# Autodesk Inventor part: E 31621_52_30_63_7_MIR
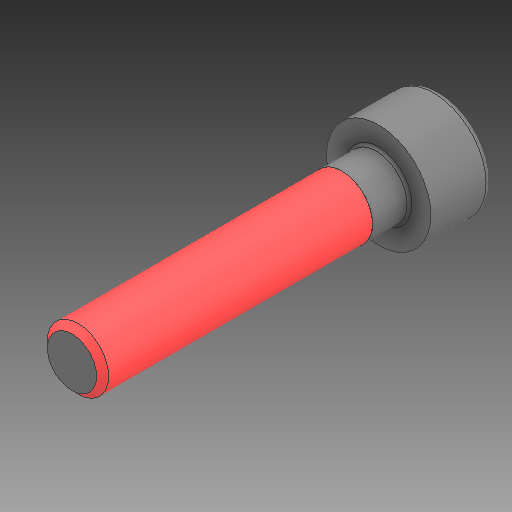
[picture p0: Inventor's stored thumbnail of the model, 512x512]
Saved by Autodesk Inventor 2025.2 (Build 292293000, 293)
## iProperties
Created: 2025-03
Part Number: E 31621_52_30_63_7_MIR
Material: Všeobecné
Document SubType Name: Modeling
Designer: Patrik
Stock Number: E 31621_52_30_63
Mass: 0.73741 g
Surface Area: 6.62537 cm^2
Volume: 0.73741 cm^3
Density: 1 g/cm^3
Appearance: Výchozí
Author: Patrik
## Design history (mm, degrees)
derived "E 31621_52_30_63_7.ipt"
feature "Těleso1::E 31621_52_30_63_7.ipt" dims "d0" = 10
tag "Prvek štítků1"
node "Těleso1"
